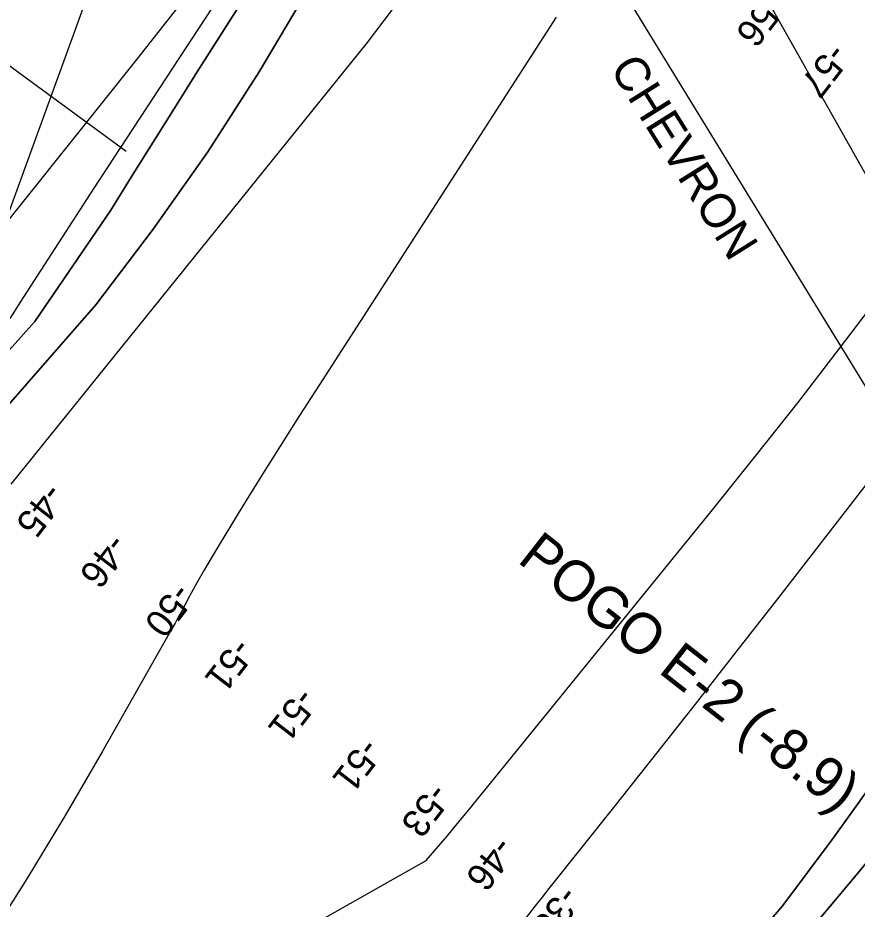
# Model space of a CAD drawing. Extents: x 3913936 to 3933962, y 195330 to 217741.
# Drawn here: x 3922950 to 3923978, y 201638 to 202729 of the extents above; entities that cross this region are included whole.
import ezdxf

# ---------------------------------------------------------------- set-up
doc = ezdxf.new("R2010")
doc.units = 0
for name, color, linetype in [('V-ANNO-TEXT', 7, 'Continuous'), ('V-CHAN-NAID', 7, 'Continuous'), ('V-LEVE-TOET', 7, 'Continuous'), ('V-RIVR-RANG', 7, 'Continuous'), ('V-TOPO-DPTH', 7, 'Continuous'), ('V-TOPO-MAJR', 7, 'Continuous'), ('V-TOPO-MINR', 7, 'Continuous'), ('V-UTIL-IDEN', 7, 'Continuous'), ('V-UTIL-LINE', 7, 'Continuous')]:
    doc.layers.add(name, color=color, linetype=linetype)

msp = doc.modelspace()

# ---------------------------------------------------------------- linework, layer by layer
at = {"layer": 'V-ANNO-TEXT'}
msp.add_lwpolyline([(3923713.2, 204620.6), (3922595.3, 201547.1)], dxfattribs=at)
at = {"layer": 'V-LEVE-TOET'}
msp.add_line((3922881.9, 202712.8), (3923082.7, 202566), dxfattribs=at)
at = {"layer": 'V-TOPO-DPTH'}
for points in [[(3923857.9, 203782), (3923855.4, 203777.6), (3923834.6, 203742.4), (3923834.2, 203741.9), (3923833.8, 203741.6), (3923832.6, 203741.6), (3923416.8, 203134.1), (3923411.8, 203125.9), (3923406.8, 203117.6), (3923401.8, 203109.5), (3923396.8, 203101.3), (3923389.6, 203089.6), (3923388.1, 203087.3), (3923386.6, 203084.9), (3923385.1, 203082.6), (3923383.6, 203080.3), (3923293.4, 202946.7), (3923245.9, 202878.3), (3923197.4, 202810.6), (3923147.2, 202744.1), (3923095.9, 202678.5), (3922791.1, 202297.8)], [(3922202.3, 201498.8), (3922970.9, 202357.5), (3923064, 202493.6), (3923089, 202534), (3923130.7, 202601), (3923172.6, 202667.7), (3923214.8, 202734.3), (3923257.1, 202800.8), (3923394.8, 203015.7), (3923408.2, 203036.7), (3923421.7, 203057.7), (3923435.1, 203078.8), (3923448.5, 203099.8), (3923524.4, 203218.8), (3923575.8, 203299.3), (3923627.1, 203379.9), (3923678.3, 203460.5), (3923729.5, 203541.2), (3923871.3, 203718.3), (3923873.2, 203720.5), (3923889.5, 203748)], [(3922202.3, 201498.8), (3922970.9, 202357.5), (3923064, 202493.6), (3923089, 202534), (3923130.7, 202601), (3923172.6, 202667.7), (3923214.8, 202734.3), (3923257.1, 202800.8), (3923394.8, 203015.7), (3923408.2, 203036.7), (3923421.7, 203057.7), (3923435.1, 203078.8), (3923448.5, 203099.8), (3923524.4, 203218.8), (3923575.8, 203299.3), (3923627.1, 203379.9), (3923678.3, 203460.5), (3923729.5, 203541.2), (3923871.3, 203718.3), (3923873.2, 203720.5), (3923889.5, 203748), (3923909.8, 203692)], [(3923304.9, 202762.9), (3923245.4, 202663), (3923182.8, 202565.2), (3923115.7, 202470.4), (3923045.6, 202377.7), (3922233.8, 201449.6)], [(3922233.8, 201449.6), (3923045.6, 202377.7), (3923115.7, 202470.4), (3923182.8, 202565.2), (3923245.4, 202663), (3923304.9, 202762.9)], [(3923021.8, 200905.6), (3923325.7, 201305.9), (3923368.5, 201362.2), (3923411.4, 201418.4), (3923454.5, 201474.4), (3923497.6, 201530.5), (3923567.7, 201621.2), (3923575.9, 201631.7), (3923584.2, 201642.3), (3923592.5, 201652.8), (3923600.8, 201663.3), (3923683.1, 201766.6), (3923732.5, 201828.9), (3923781.7, 201891.2), (3923830.7, 201953.8), (3923879.5, 202016.5), (3924180.8, 202405.3), (3924195.7, 202425.2), (3924210.1, 202445.3), (3924223.8, 202465.9), (3924237.1, 202486.8), (3924308.9, 202604.3), (3924356.9, 202684.8), (3924403.7, 202765.8)], [(3923021.8, 200905.6), (3923325.7, 201305.9), (3923368.5, 201362.2), (3923411.4, 201418.4), (3923454.5, 201474.4), (3923497.6, 201530.5), (3923567.7, 201621.2), (3923575.9, 201631.7), (3923584.2, 201642.3), (3923592.5, 201652.8), (3923600.8, 201663.3), (3923683.1, 201766.6), (3923732.5, 201828.9), (3923781.7, 201891.2), (3923830.7, 201953.8), (3923879.5, 202016.5), (3924180.8, 202405.3), (3924195.7, 202425.2), (3924210.1, 202445.3), (3924223.8, 202465.9), (3924237.1, 202486.8), (3924308.9, 202604.3), (3924356.9, 202684.8), (3924403.7, 202765.8)], [(3923130.1, 200754.5), (3923887, 201642.6), (3923917.4, 201682.8), (3923947.3, 201723.3), (3923976.7, 201764.2), (3924341.1, 202276.9), (3924356.3, 202298.5), (3924371.3, 202320.2), (3924386.1, 202342), (3924400.7, 202364), (3924531, 202562.6), (3924593.1, 202658.1), (3924654.6, 202753.8)], [(3924654.6, 202753.8), (3924593.1, 202658.1), (3924531, 202562.6), (3924400.7, 202364), (3924386.1, 202342), (3924371.3, 202320.2), (3924356.3, 202298.5), (3924341.1, 202276.9), (3923976.7, 201764.2), (3923947.3, 201723.3), (3923917.4, 201682.8), (3923887, 201642.6), (3923130.1, 200754.5)], [(3923408.5, 202739.5), (3923378, 202699), (3922941.4, 202158.5)], [(3923408.5, 202739.5), (3923378, 202699), (3922941.4, 202158.5)], [(3923354, 200902.9), (3923403.9, 200968.9), (3923454.7, 201034.2), (3923505.9, 201099.2), (3923816.3, 201488.4), (3923819.3, 201492.1), (3923822.4, 201495.7), (3923824, 201497.5), (3923827.1, 201501), (3923828.6, 201502.9), (3923978.8, 201682.2), (3924054.5, 201774.4), (3924129.1, 201867.4), (3924202, 201961.9), (3924273.6, 202057.2), (3924414.8, 202248.8), (3924423.6, 202260.8), (3924432.3, 202272.8), (3924440.8, 202285), (3924449.3, 202297.2), (3924696.7, 202658.3), (3924745.2, 202729.8)], [(3924745.2, 202729.8), (3924696.7, 202658.3), (3924449.3, 202297.2), (3924440.8, 202285), (3924432.3, 202272.8), (3924423.6, 202260.8), (3924414.8, 202248.8), (3924273.6, 202057.2), (3924202, 201961.9), (3924129.1, 201867.4), (3924054.5, 201774.4), (3923978.8, 201682.2), (3923828.6, 201502.9), (3923827.1, 201501), (3923824, 201497.5), (3923822.4, 201495.7), (3923819.3, 201492.1), (3923816.3, 201488.4), (3923505.9, 201099.2), (3923454.7, 201034.2), (3923403.9, 200968.9), (3923354, 200902.9)]]:
    msp.add_lwpolyline(points, dxfattribs=at)
at = {"layer": 'V-TOPO-MAJR'}
for points in [[(3922887.7, 201379.9), (3923450, 201697.6), (3923462.9, 201712.4), (3923475.7, 201727.3), (3923488.3, 201742.4), (3923500.8, 201757.6), (3923800.8, 202127), (3923853.3, 202192.3), (3923905.2, 202258), (3923956.4, 202324.3), (3924007.1, 202391), (3924096.6, 202510), (3924102.1, 202517.5), (3924107.5, 202525.1), (3924112.7, 202532.8), (3924117.7, 202540.6), (3924149.5, 202591), (3924169.9, 202624.3), (3924189.9, 202657.9), (3924209.1, 202692), (3924227.8, 202726.3), (3924240.2, 202749.5)], [(3923609.4, 202729.9), (3923594, 202706), (3923318.9, 202279.7), (3923295, 202242.4), (3923271.2, 202205), (3923247.8, 202167.4), (3923224.5, 202129.7), (3923197.7, 202086), (3923188.1, 202069.9), (3923178.6, 202053.8), (3923169.4, 202037.5), (3923160.4, 202021.2), (3923149.5, 202000.9), (3923146, 201994.6), (3923142.6, 201988.3), (3923139.1, 201982), (3923135.5, 201975.7), (3923053.5, 201830.7), (3923008, 201752.5), (3922961.2, 201675.1), (3922912.6, 201598.9)]]:
    msp.add_lwpolyline(points, dxfattribs=at)
at = {"layer": 'V-TOPO-MINR'}
for points in [[(3923857.9, 203782), (3923855.4, 203777.6), (3923834.6, 203742.4), (3923834.2, 203741.9), (3923833.8, 203741.6), (3923832.6, 203741.6), (3923416.8, 203134.1), (3923411.8, 203125.9), (3923406.8, 203117.6), (3923401.8, 203109.5), (3923396.8, 203101.3), (3923389.6, 203089.6), (3923388.1, 203087.3), (3923386.6, 203084.9), (3923385.1, 203082.6), (3923383.6, 203080.3), (3923293.4, 202946.7), (3923245.9, 202878.3), (3923197.4, 202810.6), (3923147.2, 202744.1), (3923095.9, 202678.5), (3922791.1, 202297.8)], [(3923873.7, 203765), (3923854.1, 203731.8), (3923563.2, 203326.1), (3923536.8, 203283.6), (3923510.4, 203241.1), (3923483.9, 203198.6), (3923457.3, 203156.2), (3923418.9, 203094.8), (3923411.5, 203083.1), (3923404, 203071.4), (3923396.5, 203059.8), (3923389, 203048.2), (3923043.2, 202520.5), (3923021.5, 202487.2), (3922999.8, 202453.9), (3922978.2, 202420.5), (3922956.7, 202387), (3922940, 202361)], [(3923889.5, 203748), (3923873.2, 203720.5), (3923871.3, 203718.3), (3923729.5, 203541.2), (3923678.3, 203460.5), (3923627.1, 203379.9), (3923575.8, 203299.3), (3923524.4, 203218.8), (3923448.5, 203099.8), (3923435.1, 203078.8), (3923421.7, 203057.7), (3923408.2, 203036.7), (3923394.8, 203015.7), (3923257.1, 202800.8), (3923214.8, 202734.3), (3923172.6, 202667.7), (3923130.7, 202601), (3923089, 202534), (3923064, 202493.6), (3922970.9, 202357.5), (3922202.3, 201498.8)], [(3923304.9, 202762.9), (3923245.4, 202663), (3923182.8, 202565.2), (3923115.7, 202470.4), (3923045.6, 202377.7), (3922233.8, 201449.6)], [(3923021.8, 200905.6), (3923325.7, 201305.9), (3923368.5, 201362.2), (3923411.4, 201418.4), (3923454.5, 201474.4), (3923497.6, 201530.5), (3923567.7, 201621.2), (3923575.9, 201631.7), (3923584.2, 201642.3), (3923592.5, 201652.8), (3923600.8, 201663.3), (3923683.1, 201766.6), (3923732.5, 201828.9), (3923781.7, 201891.2), (3923830.7, 201953.8), (3923879.5, 202016.5), (3924180.8, 202405.3), (3924195.7, 202425.2), (3924210.1, 202445.3), (3924223.8, 202465.9), (3924237.1, 202486.8), (3924308.9, 202604.3), (3924356.9, 202684.8), (3924403.7, 202765.8)], [(3923130.1, 200754.5), (3923887, 201642.6), (3923917.4, 201682.8), (3923947.3, 201723.3), (3923976.7, 201764.2), (3924341.1, 202276.9), (3924356.3, 202298.5), (3924371.3, 202320.2), (3924386.1, 202342), (3924400.7, 202364), (3924531, 202562.6), (3924593.1, 202658.1), (3924654.6, 202753.8)], [(3923408.5, 202739.5), (3923378, 202699), (3922941.4, 202158.5)], [(3923354, 200902.9), (3923403.9, 200968.9), (3923454.7, 201034.2), (3923505.9, 201099.2), (3923816.3, 201488.4), (3923819.3, 201492.1), (3923822.4, 201495.7), (3923824, 201497.5), (3923827.1, 201501), (3923828.6, 201502.9), (3923978.8, 201682.2), (3924054.5, 201774.4), (3924129.1, 201867.4), (3924202, 201961.9), (3924273.6, 202057.2), (3924414.8, 202248.8), (3924423.6, 202260.8), (3924432.3, 202272.8), (3924440.8, 202285), (3924449.3, 202297.2), (3924696.7, 202658.3), (3924745.2, 202729.8)]]:
    msp.add_lwpolyline(points, dxfattribs=at)
at = {"layer": 'V-UTIL-LINE'}
for points in [[(3926953.8, 204871.7), (3926114.5, 203439.2), (3924358.1, 201675.2), (3923230.9, 203513.5)], [(3924378.5, 201846.6), (3923455.6, 203482.7), (3923464.3, 203499.9)]]:
    msp.add_lwpolyline(points, dxfattribs=at)

# ---------------------------------------------------------------- texts
at = {"layer": 'V-CHAN-NAID'}
msp.add_text('POGO E-2 (-8.9)', height=50, rotation=321.957, dxfattribs=at).set_placement((3923560.5, 202063.7))
at = {"layer": 'V-RIVR-RANG'}
for s, rotation, p in [('-56', 232.1655, (3923867.6, 202762.3)), ('-57', 232.1655, (3923945.9, 202700.2)), ('-45', 232.4381, (3922985.4, 202162)), ('-46', 232.4381, (3923063.5, 202099.8)), ('-50', 232.4381, (3923142.8, 202039.5)), ('-51', 232.4381, (3923216.8, 201972.2)), ('-51', 232.4381, (3923294.3, 201911.4)), ('-51', 232.4381, (3923373.2, 201849.6)), ('-53', 232.4381, (3923457.3, 201794.6)), ('-46', 232.4381, (3923536.6, 201729.1)), ('-38', 232.4381, (3923617.1, 201668.8))]:
    msp.add_text(s, height=33.5, rotation=rotation, dxfattribs=at).set_placement(p)
at = {"layer": 'V-UTIL-IDEN'}
msp.add_text('CHEVRON', height=42, rotation=302.031, dxfattribs=at).set_placement((3923674.2, 202667.2))

doc.saveas('drawing.dxf')
